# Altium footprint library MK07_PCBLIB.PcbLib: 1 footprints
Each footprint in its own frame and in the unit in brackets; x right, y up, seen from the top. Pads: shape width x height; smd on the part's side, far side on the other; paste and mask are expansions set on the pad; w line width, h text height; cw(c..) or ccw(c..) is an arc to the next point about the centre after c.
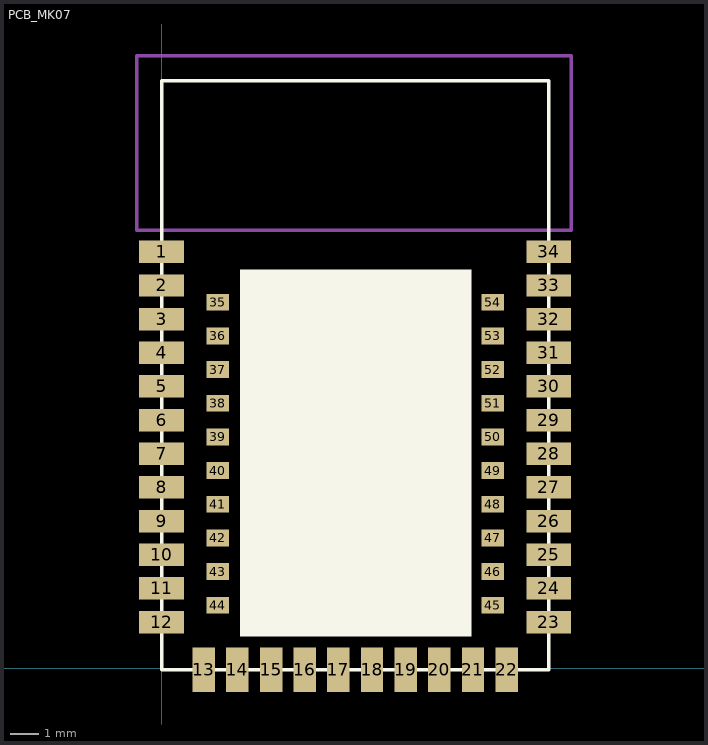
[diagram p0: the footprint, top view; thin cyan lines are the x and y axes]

## PCB_MK07 [mm] "21*13.8mm"
height 2
pads (54):
  rect 1.6x0.8 smd: 1(0,14.855) 2(0,13.655) 3(0,12.455) 4(0,11.255) 5(0,10.055) 6(0,8.855) 7(0,7.655) 8(0,6.455) 9(0,5.255) 10(0,4.055) 11(0,2.855) 12(0,1.655) 23(13.8,1.655) 24(13.8,2.855) 25(13.8,4.055) 26(13.8,5.255) 27(13.8,6.455) 28(13.8,7.655) 29(13.8,8.855) 30(13.8,10.055) 31(13.8,11.255) 32(13.8,12.455) 33(13.8,13.655) 34(13.8,14.855)
  rect 0.8x1.6 smd: 13(1.5,-0.045) 14(2.7,-0.045) 15(3.9,-0.045) 16(5.1,-0.045) 17(6.3,-0.045) 18(7.5,-0.045) 19(8.7,-0.045) 20(9.9,-0.045) 21(11.1,-0.045) 22(12.3,-0.045)
  rect 0.8x0.6 smd: 35(2,13.055) 36(2,11.855) 37(2,10.655) 38(2,9.455) 39(2,8.255) 40(2,7.055) 41(2,5.855) 42(2,4.655) 43(2,3.455) 44(2,2.255) 45(11.8,2.255) 46(11.8,3.455) 47(11.8,4.655) 48(11.8,5.855) 49(11.8,7.055) 50(11.8,8.255) 51(11.8,9.455) 52(11.8,10.655) 53(11.8,11.855) 54(11.8,13.055)
Top Overlay:
  rectangle: 2.794,1.143 11.049,14.224
  lines w0.127: 0,-0.045 0,20.955 13.8,20.955 13.8,-0.045 0,-0.045
Mechanical 2:
  lines w0.127: -0.889,15.621 -0.889,21.844 14.605,21.844 14.605,15.621 -0.889,15.621
  text "No ground pad" at 3.937,18.288 h0.51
